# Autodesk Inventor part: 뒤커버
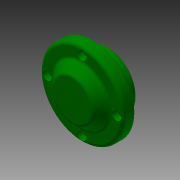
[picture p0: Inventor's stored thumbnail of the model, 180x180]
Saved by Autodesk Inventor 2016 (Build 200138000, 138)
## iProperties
Created: 2017-08
Part Number: 뒤커버
Material: 알루미늄 6061
Document SubType Name: Modeling
Designer: mduedu
Density: 2.71 g/cm^3
Appearance: 알루미늄 - 평지
Author: mduedu
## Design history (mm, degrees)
sketch "스케치1"
  geometry: C1 r 35 at (0, 0); 1 further point
  constraints: 1 centre point, 1 coincident
  dimensions: "d0" = 70 diameter of C1
extrude "돌출1" new body sketch "스케치1" distance "d1" = 10; taper "d2" = 0 deg
sketch "스케치2"
  geometry: C1 r 24 at (0, 0); 1 further point
  constraints: 1 centre point, 1 coincident
  dimensions: "d3" = 48 diameter of C1
node "작업 평면1"
sketch "스케치3"
  geometry: C1 r 17 at (0, 0); 1 further point
  constraints: 1 centre point, 1 coincident
  dimensions: "d5" = 34 diameter of C1
feature "로프트1" sketch "스케치3" dims "d6" = 0, "d7" = 90 deg, "d8" = 0, "d9" = 90 deg
sketch "스케치4"
  geometry: C1 r 24 at (0, 0) reference; 1 further point
extrude "돌출2" join sketch "스케치4" distance "d10" = 12; taper "d11" = 0 deg
hole "구멍1" diameter "d14" = 40; stored, may be unused: countersink angle "d18" = 90 deg, drill point angle "d20" = 0 deg; dims "d15" = 6, "d16" = 4, "d17" = 2, "d19" = 12, "d64" = 10, "d65" = 10
hole "구멍2" diameter "d23" = 36; stored, may be unused: countersink angle "d27" = 90 deg, drill point angle "d29" = 0 deg; dims "d24" = 6, "d25" = 4, "d26" = 2, "d28" = 8, "d62" = 10, "d63" = 10
chamfer "모따기1" distance "d39" = 1; stored, may be unused: second distance "d40" = 2, angle "d41" = 45 deg
fillet "모깎기1" dims "d42" = 0.3
fillet "모깎기2" dims "d43" = 3
sketch "스케치5" dims "d44" = 58
  geometry: 6 further points
  constraints: 2 vertical alignment, 1 coincident, 7 other
  dimensions: "d47" = 360 deg dimension on point (0, 0) point (0, 29) (derived)
sketch "스케치6"
  geometry: 4 further points
  constraints: 4 other
hole "구멍4" sketch "스케치6" at (0, 29), (-29, 0), (29, 0), (0, -29) diameter "d49" = 4.5; stored, may be unused: countersink angle "d53" = 90 deg, drill point angle "d55" = 0 deg; dims "d50" = 6, "d51" = 8, "d52" = 4.6, "d54" = 8
fillet "모깎기3" dims "d56" = 3
fillet "모깎기4" dims "d57" = 3
fillet "모깎기5" dims "d58" = 3
chamfer "모따기2" distance "d59" = 1; stored, may be unused: second distance "d60" = 2, angle "d61" = 45 deg
node "솔리드1"
other parameters: "d4" = 8
